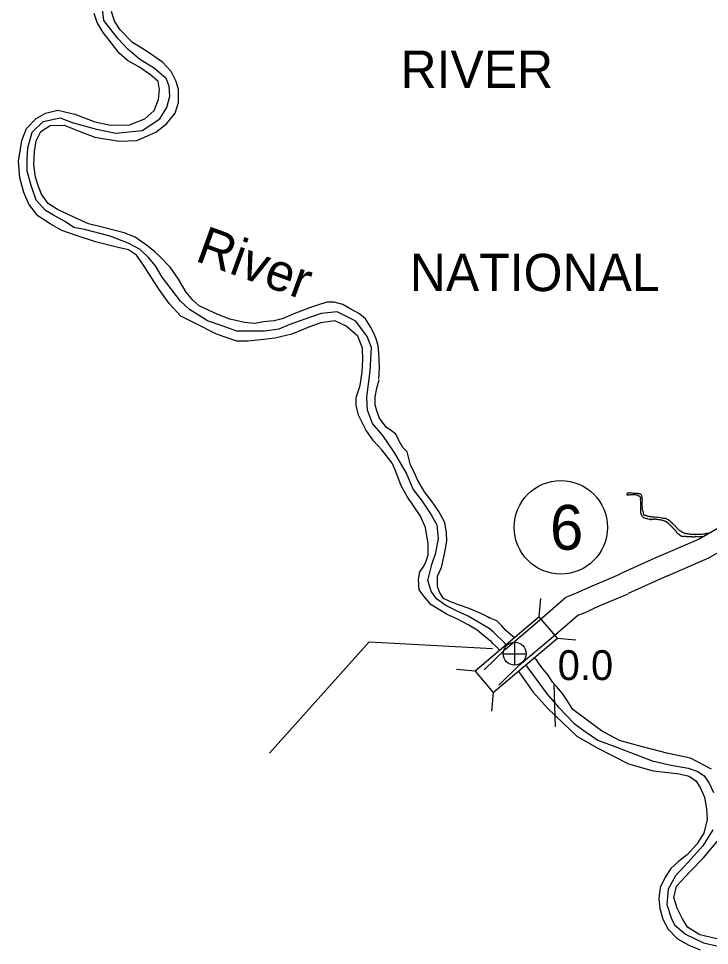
# Model space of a CAD drawing. Extents: x -939622 to -934222, y 1383701 to 1385301.
# Drawn here: x -935949.19 to -935919.88, y 1383950.49 to 1383989.81 of the extents above; entities that cross this region are included whole.
import ezdxf

# ---------------------------------------------------------------- set-up
doc = ezdxf.new("R2010")
doc.units = 0
for name, color, linetype in [('Level 10', 7, 'Continuous'), ('Level 2', 7, 'Continuous'), ('Level 20', 7, 'Continuous'), ('Level 25', 7, 'Continuous'), ('Level 26', 7, 'Continuous'), ('Level 27', 7, 'Continuous'), ('Level 7', 7, 'Continuous'), ('Level 9', 7, 'Continuous')]:
    doc.layers.add(name, color=color, linetype=linetype)

msp = doc.modelspace()

# ---------------------------------------------------------------- linework, layer by layer
at = {"layer": 'Level 10'}
for points in [[(-935916.342, 1383970.275), (-935917.942, 1383969.097), (-935920.327, 1383967.721), (-935922.032, 1383966.99)], [(-935915.808, 1383969.55), (-935917.449, 1383968.343), (-935919.923, 1383966.914), (-935921.678, 1383966.163)], [(-935922.041, 1383966.986), (-935923.698, 1383966.236)], [(-935925.97, 1383965.261), (-935925.842, 1383965.319), (-935925.451, 1383965.471), (-935925.147, 1383965.621), (-935924.839, 1383965.75), (-935923.689, 1383966.24)], [(-935921.669, 1383966.167), (-935923.327, 1383965.416)], [(-935925.48, 1383964.494), (-935925.493, 1383964.489), (-935925.089, 1383964.646), (-935924.774, 1383964.801), (-935924.489, 1383964.921), (-935923.336, 1383965.412)], [(-935929.446, 1383962.18), (-935928.542, 1383963.06), (-935927.195, 1383964.198), (-935925.97, 1383965.261)], [(-935928.819, 1383961.535), (-935927.937, 1383962.393), (-935926.609, 1383963.514), (-935925.48, 1383964.494)]]:
    msp.add_lwpolyline(points, dxfattribs=at)
at = {"layer": 'Level 2'}
for points in [[(-935929.235, 1383963.93), (-935929.64, 1383964.17), (-935930.126, 1383964.455), (-935930.585, 1383964.676), (-935931.065, 1383964.906), (-935931.467, 1383965.197), (-935931.693, 1383965.515), (-935931.833, 1383965.978), (-935931.661, 1383966.646), (-935931.498, 1383967.152), (-935931.383, 1383967.748), (-935931.433, 1383968.322), (-935931.732, 1383968.841), (-935932.051, 1383969.34), (-935932.454, 1383969.844), (-935932.741, 1383970.523), (-935933.235, 1383971.379), (-935933.741, 1383972.123), (-935934.174, 1383972.636), (-935934.386, 1383973.201), (-935934.424, 1383973.757), (-935934.275, 1383974.858), (-935934.218, 1383975.86), (-935934.4, 1383976.323), (-935934.89, 1383976.968), (-935935.674, 1383977.369), (-935936.359, 1383977.304), (-935937.044, 1383977.053), (-935937.679, 1383976.831), (-935938.145, 1383976.629), (-935938.756, 1383976.546), (-935939.927, 1383976.549), (-935940.56, 1383976.773), (-935941.175, 1383976.982), (-935941.935, 1383977.476), (-935942.328, 1383977.827), (-935943.099, 1383978.838), (-935943.388, 1383979.325), (-935943.698, 1383979.691), (-935944.034, 1383980.015), (-935944.542, 1383980.284), (-935945.306, 1383980.586), (-935946.398, 1383980.866), (-935946.847, 1383980.955), (-935947.208, 1383981.183), (-935947.709, 1383981.473), (-935948.045, 1383981.671), (-935948.451, 1383982.103), (-935948.663, 1383982.725), (-935948.824, 1383983.332), (-935948.832, 1383983.816), (-935948.794, 1383984.333), (-935948.614, 1383984.992), (-935948.151, 1383985.442), (-935947.424, 1383985.594), (-935946.917, 1383985.4), (-935946.356, 1383985.245), (-935945.882, 1383985.123), (-935945.064, 1383984.947), (-935943.956, 1383985.067), (-935943.203, 1383985.56), (-935942.902, 1383986.035), (-935942.778, 1383986.523), (-935942.797, 1383986.944), (-935942.93, 1383987.271), (-935943.42, 1383987.688), (-935944.065, 1383988.095), (-935944.564, 1383988.518), (-935944.973, 1383988.95), (-935945.575, 1383989.725), (-935945.655, 1383990.458)], [(-935928.516, 1383963.257), (-935928.569, 1383963.318), (-935928.715, 1383963.463), (-935928.866, 1383963.594), (-935929.047, 1383963.786), (-935929.235, 1383963.93)], [(-935927.675, 1383962.404), (-935927.596, 1383962.286), (-935927.24, 1383961.787), (-935926.77, 1383961.145), (-935926.281, 1383960.596), (-935925.62, 1383959.901), (-935925.155, 1383959.562), (-935924.626, 1383959.204), (-935923.784, 1383958.884), (-935922.308, 1383958.318), (-935921.509, 1383958.135), (-935920.789, 1383958.005), (-935920.383, 1383957.872), (-935920.111, 1383957.69), (-935919.893, 1383957.377), (-935919.711, 1383956.979)], [(-935919.745, 1383955.393), (-935920.159, 1383954.717), (-935920.781, 1383954.017), (-935921.326, 1383953.437), (-935921.64, 1383952.872), (-935921.694, 1383952.229), (-935921.505, 1383951.66), (-935921.365, 1383951.369), (-935920.907, 1383950.964), (-935920.135, 1383950.594), (-935919.149, 1383950.378)]]:
    msp.add_lwpolyline(points, dxfattribs=at)
at = {"layer": 'Level 20'}
for p, q in [((-935927.103, 1383964.426), (-935927.037, 1383965.215)), ((-935926.336, 1383963.519), (-935925.547, 1383963.452)), ((-935929.826, 1383962.127), (-935930.615, 1383962.193)), ((-935929.059, 1383961.219), (-935929.126, 1383960.43))]:
    msp.add_line(p, q, dxfattribs=at)
msp.add_lwpolyline([(-935929.059, 1383961.219), (-935926.336, 1383963.519), (-935927.103, 1383964.426), (-935929.826, 1383962.127)], close=True, dxfattribs=at)
at = {"layer": 'Level 25'}
msp.add_lwpolyline([(-935938.545, 1383958.645), (-935934.316, 1383963.373), (-935929.092, 1383963.083)], dxfattribs=at)
at = {"layer": 'Level 26'}
for p, q in [((-935928.147, 1383962.379), (-935928.147, 1383963.354)), ((-935928.635, 1383962.866), (-935927.66, 1383962.866))]:
    msp.add_line(p, q, dxfattribs=at)
msp.add_circle((-935928.147, 1383962.866), 0.487, dxfattribs=at)
at = {"layer": 'Level 27'}
msp.add_circle((-935926.189, 1383968.228), 1.98, dxfattribs=at)
at = {"layer": 'Level 7'}
msp.add_lwpolyline([(-935926.417, 1383959.763), (-935926.472, 1383961.567)], dxfattribs=at)
at = {"layer": 'Level 9'}
for points in [[(-935929.249, 1383963.46), (-935929.743, 1383963.866), (-935930.097, 1383964.073), (-935930.566, 1383964.327), (-935931.016, 1383964.528), (-935931.334, 1383964.722), (-935931.688, 1383964.935), (-935931.983, 1383965.289), (-935932.197, 1383965.58), (-935932.225, 1383966.019), (-935932.172, 1383966.338), (-935932.032, 1383966.54), (-935931.913, 1383966.751), (-935931.815, 1383967.067), (-935931.814, 1383967.527), (-935931.924, 1383968.227), (-935932.148, 1383968.705), (-935932.711, 1383969.539), (-935932.964, 1383969.987), (-935933.109, 1383970.368), (-935933.23, 1383970.702), (-935933.339, 1383970.951), (-935933.784, 1383971.51), (-935934.139, 1383971.9), (-935934.467, 1383972.368), (-935934.775, 1383972.984), (-935934.875, 1383973.416), (-935934.876, 1383973.741), (-935934.704, 1383974.247), (-935934.616, 1383974.818), (-935934.591, 1383975.339), (-935934.605, 1383975.835), (-935934.807, 1383976.334), (-935935.294, 1383976.762), (-935935.78, 1383976.987), (-935936.364, 1383976.91), (-935936.873, 1383976.725), (-935937.596, 1383976.42), (-935938.327, 1383976.252), (-935938.92, 1383976.185), (-935939.447, 1383976.123), (-935939.935, 1383976.125), (-935940.799, 1383976.429), (-935941.663, 1383976.86), (-935942.314, 1383977.192), (-935942.81, 1383977.726), (-935943.229, 1383978.312), (-935943.563, 1383978.846), (-935943.924, 1383979.39), (-935944.192, 1383979.771), (-935944.523, 1383980.005), (-935944.969, 1383980.097), (-935945.935, 1383980.338), (-935946.744, 1383980.612), (-935947.359, 1383980.815), (-935947.849, 1383981.1), (-935948.374, 1383981.45), (-935948.756, 1383981.942), (-935948.97, 1383982.432), (-935949.143, 1383983.054), (-935949.194, 1383983.764), (-935949.059, 1383984.633), (-935948.851, 1383985.145), (-935948.439, 1383985.576), (-935948.048, 1383985.797), (-935947.527, 1383985.921), (-935946.801, 1383985.752), (-935945.952, 1383985.435), (-935945.29, 1383985.287), (-935944.487, 1383985.307), (-935943.832, 1383985.561), (-935943.438, 1383985.914), (-935943.257, 1383986.38), (-935943.21, 1383986.802), (-935943.268, 1383987.144), (-935943.602, 1383987.423), (-935944.097, 1383987.762), (-935944.569, 1383988.034), (-935944.929, 1383988.34), (-935945.248, 1383988.766), (-935945.6, 1383989.222), (-935945.859, 1383989.643), (-935945.986, 1383990.021)], [(-935933.908, 1383974.513), (-935933.894, 1383974.751), (-935933.88, 1383975.04), (-935933.893, 1383975.338), (-935933.903, 1383975.62), (-935933.931, 1383975.93), (-935934.004, 1383976.176), (-935934.116, 1383976.471), (-935934.266, 1383976.741), (-935934.48, 1383977.08), (-935934.724, 1383977.284), (-935935.099, 1383977.485), (-935935.441, 1383977.679), (-935935.81, 1383977.781), (-935936.097, 1383977.777), (-935936.391, 1383977.701), (-935936.854, 1383977.54), (-935937.225, 1383977.392), (-935937.522, 1383977.292), (-935938.015, 1383977.074), (-935938.347, 1383976.995), (-935938.799, 1383976.94), (-935939.174, 1383976.879), (-935939.614, 1383976.923), (-935940.229, 1383977.053), (-935940.745, 1383977.257), (-935941.537, 1383977.625), (-935941.801, 1383977.864), (-935942.078, 1383978.21), (-935942.406, 1383978.759), (-935942.768, 1383979.263), (-935943.198, 1383979.719), (-935943.426, 1383979.926), (-935943.765, 1383980.199), (-935944.249, 1383980.532), (-935944.708, 1383980.723), (-935945.592, 1383980.949), (-935946.219, 1383981.11), (-935946.855, 1383981.388), (-935947.548, 1383981.705), (-935947.941, 1383981.972), (-935948.215, 1383982.362), (-935948.348, 1383982.683), (-935948.472, 1383983.077), (-935948.546, 1383983.615), (-935948.521, 1383984.172), (-935948.451, 1383984.632), (-935948.249, 1383985.017), (-935947.854, 1383985.28), (-935947.261, 1383985.293), (-935946.628, 1383985.042), (-935945.953, 1383984.786), (-935944.922, 1383984.608), (-935944.179, 1383984.646), (-935943.366, 1383984.991), (-935942.915, 1383985.347), (-935942.548, 1383985.799), (-935942.406, 1383986.25), (-935942.407, 1383986.807), (-935942.504, 1383987.143), (-935942.716, 1383987.561), (-935943.082, 1383987.957), (-935943.593, 1383988.31), (-935943.92, 1383988.535), (-935944.365, 1383988.798), (-935944.879, 1383989.335), (-935945.129, 1383989.705), (-935945.253, 1383990.119)], [(-935929.279, 1383964.428), (-935929.218, 1383964.391), (-935929.485, 1383964.523), (-935930.076, 1383964.786), (-935930.532, 1383964.935), (-935930.904, 1383965.084), (-935931.165, 1383965.204), (-935931.337, 1383965.483), (-935931.421, 1383965.72), (-935931.426, 1383966.157), (-935931.25, 1383966.524), (-935931.159, 1383966.978), (-935931.079, 1383967.309), (-935931.018, 1383967.652), (-935931.04, 1383967.992), (-935931.116, 1383968.431), (-935931.36, 1383968.899), (-935931.68, 1383969.35), (-935931.968, 1383969.728), (-935932.27, 1383970.238), (-935932.424, 1383970.593), (-935932.56, 1383970.869), (-935932.714, 1383971.428), (-935932.898, 1383971.614), (-935933.063, 1383971.905), (-935933.193, 1383972.182), (-935933.376, 1383972.317), (-935933.593, 1383972.478), (-935933.879, 1383972.863), (-935933.996, 1383973.175), (-935934.063, 1383973.43), (-935934.064, 1383973.761), (-935934, 1383974.134), (-935933.896, 1383974.483)], [(-935922.682, 1383968.867), (-935922.692, 1383968.888), (-935922.703, 1383968.918), (-935922.713, 1383968.938), (-935922.724, 1383968.974), (-935922.731, 1383969.003), (-935922.729, 1383969.019), (-935922.733, 1383969.036), (-935922.729, 1383969.067), (-935922.726, 1383969.07), (-935922.73, 1383969.097), (-935922.732, 1383969.13), (-935922.742, 1383969.208), (-935922.744, 1383969.238), (-935922.741, 1383969.241), (-935922.737, 1383969.268), (-935922.727, 1383969.314), (-935922.732, 1383969.344), (-935922.73, 1383969.368), (-935922.731, 1383969.392), (-935922.732, 1383969.413), (-935922.733, 1383969.428), (-935922.732, 1383969.458), (-935922.736, 1383969.485), (-935922.743, 1383969.506), (-935922.746, 1383969.506), (-935922.75, 1383969.521), (-935922.743, 1383969.551), (-935922.749, 1383969.554), (-935922.759, 1383969.566), (-935922.763, 1383969.586), (-935922.769, 1383969.595), (-935922.782, 1383969.609), (-935922.798, 1383969.621), (-935922.832, 1383969.649), (-935922.838, 1383969.649), (-935922.85, 1383969.645), (-935922.868, 1383969.647), (-935922.883, 1383969.646), (-935922.904, 1383969.651), (-935922.92, 1383969.662), (-935922.923, 1383969.662), (-935922.95, 1383969.661), (-935922.977, 1383969.659), (-935923.004, 1383969.655), (-935923.006, 1383969.651), (-935923.007, 1383969.654), (-935923.022, 1383969.66), (-935923.052, 1383969.664), (-935923.077, 1383969.672), (-935923.101, 1383969.67), (-935923.11, 1383969.67), (-935923.143, 1383969.671), (-935923.167, 1383969.676), (-935923.17, 1383969.676), (-935923.191, 1383969.678), (-935923.246, 1383969.687), (-935923.273, 1383969.688), (-935923.282, 1383969.688), (-935923.3, 1383969.684), (-935923.315, 1383969.683), (-935923.333, 1383969.682), (-935923.342, 1383969.684), (-935923.354, 1383969.681), (-935923.356, 1383969.678), (-935923.362, 1383969.677), (-935923.365, 1383969.677), (-935923.377, 1383969.67), (-935923.383, 1383969.667), (-935923.379, 1383969.649), (-935923.379, 1383969.646), (-935923.381, 1383969.631), (-935923.384, 1383969.631), (-935923.378, 1383969.628), (-935923.38, 1383969.619), (-935923.383, 1383969.61), (-935923.38, 1383969.61), (-935923.365, 1383969.608), (-935923.365, 1383969.611), (-935923.356, 1383969.611), (-935923.35, 1383969.606), (-935923.344, 1383969.609), (-935923.335, 1383969.612), (-935923.308, 1383969.611), (-935923.299, 1383969.611), (-935923.29, 1383969.615), (-935923.26, 1383969.61), (-935923.254, 1383969.611), (-935923.242, 1383969.617), (-935923.236, 1383969.621), (-935923.233, 1383969.618), (-935923.203, 1383969.623), (-935923.191, 1383969.623), (-935923.164, 1383969.619), (-935923.14, 1383969.623), (-935923.137, 1383969.623), (-935923.101, 1383969.622), (-935923.071, 1383969.621), (-935923.068, 1383969.621), (-935923.041, 1383969.619), (-935923.005, 1383969.615)], [(-935923.005, 1383969.615), (-935922.974, 1383969.608), (-935922.946, 1383969.591), (-935922.921, 1383969.575), (-935922.918, 1383969.575), (-935922.906, 1383969.573), (-935922.9, 1383969.57), (-935922.879, 1383969.562), (-935922.848, 1383969.546), (-935922.825, 1383969.526), (-935922.825, 1383969.514), (-935922.822, 1383969.511), (-935922.825, 1383969.508), (-935922.821, 1383969.49), (-935922.817, 1383969.481), (-935922.806, 1383969.448), (-935922.811, 1383969.433), (-935922.822, 1383969.402), (-935922.822, 1383969.396), (-935922.815, 1383969.379), (-935922.814, 1383969.376), (-935922.823, 1383969.36), (-935922.814, 1383969.373), (-935922.801, 1383969.349), (-935922.809, 1383969.34), (-935922.812, 1383969.334), (-935922.812, 1383969.33), (-935922.809, 1383969.322), (-935922.805, 1383969.307), (-935922.807, 1383969.301), (-935922.806, 1383969.274), (-935922.808, 1383969.261), (-935922.811, 1383969.252), (-935922.813, 1383969.234), (-935922.809, 1383969.225), (-935922.811, 1383969.207), (-935922.797, 1383969.169), (-935922.802, 1383969.141), (-935922.804, 1383969.129), (-935922.803, 1383969.108), (-935922.806, 1383969.102), (-935922.808, 1383969.081), (-935922.807, 1383969.063), (-935922.809, 1383969.056), (-935922.808, 1383969.041), (-935922.811, 1383969.026), (-935922.81, 1383969.008), (-935922.812, 1383968.993), (-935922.808, 1383968.984), (-935922.807, 1383968.96), (-935922.807, 1383968.954), (-935922.806, 1383968.936), (-935922.805, 1383968.915), (-935922.807, 1383968.906), (-935922.807, 1383968.894), (-935922.806, 1383968.885), (-935922.805, 1383968.873), (-935922.804, 1383968.855), (-935922.804, 1383968.84), (-935922.797, 1383968.822), (-935922.796, 1383968.816), (-935922.795, 1383968.798), (-935922.789, 1383968.786), (-935922.785, 1383968.78), (-935922.775, 1383968.763), (-935922.772, 1383968.76), (-935922.766, 1383968.748), (-935922.759, 1383968.734), (-935922.749, 1383968.71), (-935922.742, 1383968.704), (-935922.723, 1383968.681), (-935922.704, 1383968.658), (-935922.691, 1383968.65), (-935922.685, 1383968.644), (-935922.682, 1383968.644), (-935922.654, 1383968.631), (-935922.617, 1383968.618), (-935922.59, 1383968.61), (-935922.578, 1383968.611), (-935922.526, 1383968.602), (-935922.514, 1383968.599), (-935922.511, 1383968.596), (-935922.493, 1383968.585), (-935922.444, 1383968.579), (-935922.417, 1383968.58), (-935922.411, 1383968.575), (-935922.38, 1383968.564), (-935922.344, 1383968.563)], [(-935920.6, 1383967.926), (-935920.612, 1383967.925), (-935920.652, 1383967.926), (-935920.669, 1383967.925), (-935920.709, 1383967.932), (-935920.742, 1383967.933), (-935920.763, 1383967.935), (-935920.775, 1383967.938), (-935920.784, 1383967.94), (-935920.818, 1383967.953), (-935920.839, 1383967.955), (-935920.866, 1383967.957), (-935920.882, 1383967.959), (-935920.888, 1383967.962), (-935920.93, 1383967.971), (-935920.958, 1383967.979), (-935920.986, 1383967.992), (-935920.989, 1383967.992), (-935921.013, 1383968.003), (-935921.029, 1383968.014), (-935921.05, 1383968.025), (-935921.057, 1383968.034), (-935921.076, 1383968.051), (-935921.088, 1383968.056), (-935921.095, 1383968.065), (-935921.122, 1383968.075), (-935921.137, 1383968.081), (-935921.153, 1383968.098), (-935921.176, 1383968.118), (-935921.191, 1383968.135), (-935921.192, 1383968.138), (-935921.207, 1383968.152), (-935921.235, 1383968.169), (-935921.248, 1383968.183), (-935921.261, 1383968.203), (-935921.28, 1383968.224), (-935921.293, 1383968.238), (-935921.322, 1383968.263), (-935921.328, 1383968.278), (-935921.341, 1383968.29), (-935921.366, 1383968.315), (-935921.392, 1383968.335), (-935921.395, 1383968.338), (-935921.41, 1383968.349), (-935921.423, 1383968.363), (-935921.427, 1383968.372), (-935921.433, 1383968.381), (-935921.443, 1383968.395), (-935921.462, 1383968.41), (-935921.465, 1383968.415), (-935921.487, 1383968.426), (-935921.493, 1383968.435), (-935921.518, 1383968.452), (-935921.531, 1383968.478), (-935921.538, 1383968.487), (-935921.559, 1383968.498), (-935921.585, 1383968.517), (-935921.588, 1383968.517), (-935921.597, 1383968.52), (-935921.631, 1383968.542), (-935921.64, 1383968.547), (-935921.674, 1383968.561), (-935921.709, 1383968.592), (-935921.742, 1383968.602), (-935921.752, 1383968.605), (-935921.767, 1383968.607), (-935921.773, 1383968.607), (-935921.794, 1383968.608), (-935921.803, 1383968.608), (-935921.854, 1383968.608), (-935921.872, 1383968.613), (-935922.051, 1383968.64), (-935922.079, 1383968.653), (-935922.124, 1383968.651), (-935922.127, 1383968.651), (-935922.144, 1383968.644), (-935922.196, 1383968.656), (-935922.214, 1383968.661), (-935922.259, 1383968.664), (-935922.28, 1383968.663), (-935922.295, 1383968.662), (-935922.338, 1383968.669), (-935922.389, 1383968.669), (-935922.395, 1383968.669), (-935922.407, 1383968.671), (-935922.432, 1383968.688), (-935922.468, 1383968.686), (-935922.471, 1383968.686), (-935922.477, 1383968.686), (-935922.513, 1383968.696), (-935922.52, 1383968.701), (-935922.544, 1383968.712), (-935922.569, 1383968.72), (-935922.581, 1383968.728), (-935922.633, 1383968.737), (-935922.648, 1383968.746), (-935922.661, 1383968.76), (-935922.671, 1383968.784), (-935922.676, 1383968.816), (-935922.684, 1383968.843), (-935922.682, 1383968.867)], [(-935921.725, 1383968.455), (-935921.735, 1383968.461), (-935921.741, 1383968.47), (-935921.772, 1383968.486), (-935921.775, 1383968.486), (-935921.79, 1383968.491), (-935921.803, 1383968.499), (-935921.821, 1383968.501), (-935921.839, 1383968.5), (-935921.864, 1383968.514), (-935921.876, 1383968.523), (-935921.889, 1383968.534), (-935921.895, 1383968.534), (-935921.907, 1383968.536), (-935921.913, 1383968.536), (-935921.952, 1383968.539), (-935921.98, 1383968.544), (-935921.986, 1383968.547), (-935922.019, 1383968.548), (-935922.04, 1383968.55), (-935922.077, 1383968.56), (-935922.083, 1383968.563), (-935922.086, 1383968.562), (-935922.098, 1383968.562), (-935922.137, 1383968.566), (-935922.152, 1383968.568), (-935922.167, 1383968.567), (-935922.185, 1383968.572), (-935922.201, 1383968.574), (-935922.207, 1383968.574), (-935922.209, 1383968.574), (-935922.234, 1383968.575), (-935922.242, 1383968.572), (-935922.257, 1383968.568), (-935922.269, 1383968.555), (-935922.275, 1383968.555), (-935922.284, 1383968.555), (-935922.29, 1383968.554), (-935922.302, 1383968.557), (-935922.32, 1383968.556), (-935922.332, 1383968.558), (-935922.344, 1383968.557), (-935922.38, 1383968.564)], [(-935920.333, 1383967.817), (-935920.36, 1383967.819), (-935920.408, 1383967.819), (-935920.421, 1383967.824), (-935920.461, 1383967.84), (-935920.498, 1383967.808), (-935920.504, 1383967.811), (-935920.519, 1383967.81), (-935920.534, 1383967.809), (-935920.549, 1383967.808), (-935920.555, 1383967.808), (-935920.567, 1383967.81), (-935920.585, 1383967.815), (-935920.604, 1383967.82), (-935920.631, 1383967.822), (-935920.64, 1383967.821), (-935920.652, 1383967.821), (-935920.661, 1383967.823), (-935920.682, 1383967.822), (-935920.709, 1383967.824), (-935920.727, 1383967.823), (-935920.748, 1383967.822), (-935920.76, 1383967.824), (-935920.769, 1383967.823), (-935920.787, 1383967.822), (-935920.799, 1383967.822), (-935920.82, 1383967.824), (-935920.851, 1383967.828), (-935920.881, 1383967.832), (-935920.908, 1383967.837), (-935920.935, 1383967.838), (-935920.944, 1383967.838), (-935920.968, 1383967.837), (-935920.974, 1383967.836), (-935920.989, 1383967.833), (-935921.013, 1383967.831), (-935921.028, 1383967.833), (-935921.037, 1383967.836), (-935921.049, 1383967.838), (-935921.068, 1383967.852), (-935921.08, 1383967.858), (-935921.096, 1383967.863), (-935921.102, 1383967.866), (-935921.114, 1383967.874), (-935921.124, 1383967.882), (-935921.124, 1383967.885), (-935921.133, 1383967.894), (-935921.14, 1383967.9), (-935921.146, 1383967.905), (-935921.152, 1383967.908), (-935921.168, 1383967.919), (-935921.183, 1383967.93), (-935921.193, 1383967.936), (-935921.208, 1383967.941), (-935921.218, 1383967.95), (-935921.221, 1383967.952), (-935921.246, 1383967.972), (-935921.259, 1383967.99), (-935921.262, 1383967.995), (-935921.269, 1383968.013), (-935921.269, 1383968.019), (-935921.277, 1383968.043), (-935921.292, 1383968.048), (-935921.296, 1383968.06), (-935921.299, 1383968.063), (-935921.315, 1383968.08), (-935921.339, 1383968.094), (-935921.343, 1383968.106), (-935921.372, 1383968.131), (-935921.397, 1383968.163), (-935921.404, 1383968.172), (-935921.407, 1383968.171), (-935921.404, 1383968.172), (-935921.407, 1383968.174), (-935921.416, 1383968.18), (-935921.426, 1383968.188), (-935921.429, 1383968.194), (-935921.442, 1383968.206), (-935921.445, 1383968.218), (-935921.458, 1383968.232), (-935921.477, 1383968.246), (-935921.483, 1383968.255), (-935921.49, 1383968.263), (-935921.509, 1383968.277), (-935921.519, 1383968.298), (-935921.522, 1383968.301), (-935921.541, 1383968.315), (-935921.547, 1383968.32), (-935921.56, 1383968.332), (-935921.573, 1383968.352), (-935921.579, 1383968.355), (-935921.601, 1383968.369), (-935921.601, 1383968.375), (-935921.611, 1383968.386), (-935921.629, 1383968.397), (-935921.651, 1383968.408), (-935921.667, 1383968.431), (-935921.685, 1383968.434), (-935921.698, 1383968.442), (-935921.722, 1383968.45), (-935921.725, 1383968.455)], [(-935919.902, 1383967.972), (-935919.912, 1383967.97), (-935919.918, 1383967.966), (-935919.933, 1383967.966), (-935919.963, 1383967.967), (-935919.969, 1383967.967), (-935919.984, 1383967.966), (-935919.995, 1383967.962), (-935920.025, 1383967.96), (-935920.025, 1383967.957), (-935920.025, 1383967.96), (-935920.046, 1383967.95), (-935920.049, 1383967.95), (-935920.079, 1383967.945), (-935920.091, 1383967.945), (-935920.103, 1383967.944), (-935920.126, 1383967.94), (-935920.138, 1383967.939), (-935920.201, 1383967.927), (-935920.21, 1383967.926), (-935920.222, 1383967.926), (-935920.243, 1383967.918), (-935920.263, 1383967.917), (-935920.275, 1383967.917), (-935920.324, 1383967.92), (-935920.342, 1383967.922), (-935920.369, 1383967.921), (-935920.39, 1383967.925), (-935920.414, 1383967.927), (-935920.453, 1383967.928), (-935920.471, 1383967.93), (-935920.501, 1383967.928), (-935920.513, 1383967.928), (-935920.535, 1383967.93), (-935920.567, 1383967.928), (-935920.576, 1383967.927), (-935920.6, 1383967.926)], [(-935920.125, 1383967.836), (-935920.133, 1383967.834), (-935920.178, 1383967.829), (-935920.214, 1383967.833), (-935920.246, 1383967.822), (-935920.273, 1383967.82), (-935920.297, 1383967.819), (-935920.333, 1383967.817)], [(-935928.174, 1383963.552), (-935928.245, 1383963.615), (-935928.527, 1383963.852), (-935928.692, 1383964.045), (-935928.91, 1383964.257), (-935929.111, 1383964.35), (-935929.279, 1383964.428)], [(-935928.792, 1383963.012), (-935928.912, 1383963.158), (-935929.054, 1383963.292), (-935929.151, 1383963.391), (-935929.249, 1383963.46)], [(-935927.208, 1383962.591), (-935927.345, 1383962.689)], [(-935926.747, 1383961.969), (-935926.943, 1383962.208), (-935927.121, 1383962.455), (-935927.208, 1383962.591)], [(-935928.003, 1383962.14), (-935927.968, 1383962.101), (-935927.372, 1383961.245), (-935926.741, 1383960.535), (-935926.116, 1383959.942), (-935925.515, 1383959.369), (-935924.653, 1383958.872), (-935923.321, 1383958.19), (-935922.276, 1383957.891), (-935921.157, 1383957.772), (-935920.75, 1383957.678), (-935920.456, 1383957.47), (-935920.275, 1383957.189), (-935920.101, 1383956.785), (-935920.016, 1383956.288), (-935919.988, 1383955.837), (-935920.122, 1383955.259), (-935920.415, 1383954.785), (-935920.823, 1383954.332), (-935921.178, 1383954.06), (-935921.52, 1383953.747), (-935921.768, 1383953.388), (-935921.969, 1383952.947), (-935922.031, 1383952.482), (-935921.995, 1383952.05), (-935921.863, 1383951.608), (-935921.641, 1383951.175), (-935921.24, 1383950.774), (-935920.753, 1383950.505), (-935920.274, 1383950.299)], [(-935919.798, 1383957.972), (-935920.689, 1383958.431), (-935921.691, 1383958.653), (-935922.935, 1383958.968), (-935923.706, 1383959.19), (-935924.46, 1383959.6), (-935925.241, 1383960.171), (-935925.684, 1383960.498), (-935925.923, 1383960.888), (-935926.12, 1383961.175), (-935926.374, 1383961.469), (-935926.535, 1383961.645), (-935926.747, 1383961.969)], [(-935919.332, 1383950.707), (-935920.289, 1383950.945), (-935920.813, 1383951.264), (-935921.024, 1383951.613), (-935921.252, 1383952.076), (-935921.399, 1383952.523), (-935921.275, 1383952.999), (-935920.707, 1383953.631), (-935920.136, 1383954.212), (-935919.416, 1383955.071)]]:
    msp.add_lwpolyline(points, dxfattribs=at)

# ---------------------------------------------------------------- texts
at = {"layer": 'Level 25'}
msp.add_text('0.0', height=1.2672, dxfattribs=at).set_placement((-935926.324, 1383961.747))
at = {"layer": 'Level 27'}
msp.add_text('6', height=1.901, dxfattribs=at).set_placement((-935926.649, 1383967.277))
at = {"layer": 'Level 7'}
for s, p in [('RIVER', (-935932.99, 1383986.873)), ('NATIONAL', (-935932.594, 1383978.249))]:
    msp.add_text(s, height=1.584, dxfattribs=at).set_placement(p)
at = {"layer": 'Level 9'}
msp.add_text('River', height=1.584, rotation=340, dxfattribs=at).set_placement((-935941.75, 1383979.549))

doc.saveas('drawing.dxf')
